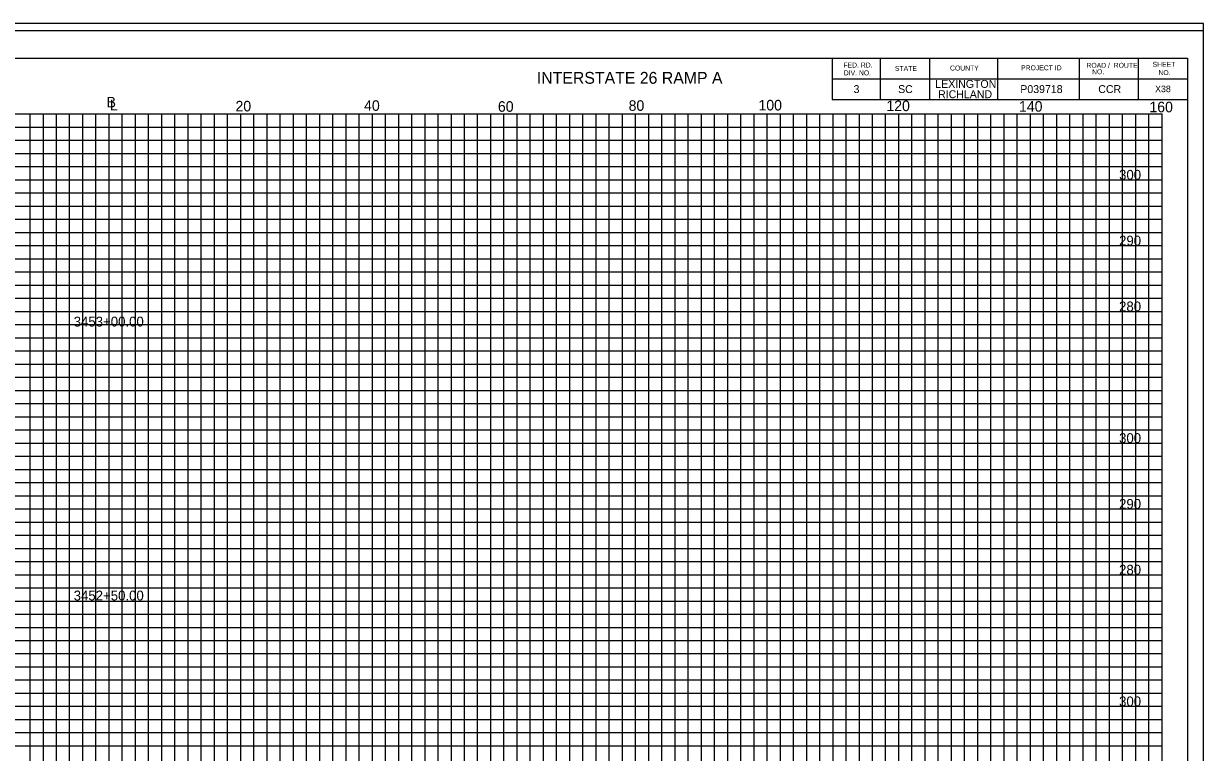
# Model space of a CAD drawing. Extents: x 967 to 1326, y 964 to 3704.
# Drawn here: x 1147 to 1326.3, y 2473 to 2583.7 of the extents above; entities that cross this region are included whole.
import ezdxf

# ---------------------------------------------------------------- set-up
doc = ezdxf.new("R2010")
doc.units = 0
for name, color, linetype in [('Default', 7, 'Continuous'), ('RD_SHT_Bndy', 7, 'Continuous'), ('RD_SHT_IplotShp', 7, 'Continuous'), ('RD_SHT_MjGrid', 7, 'Continuous'), ('RD_SHT_MnGrid', 7, 'Continuous'), ('RD_SHT_TX', 7, 'Continuous'), ('RD_XS_TX_Station', 7, 'Continuous')]:
    doc.layers.add(name, color=color, linetype=linetype)

msp = doc.modelspace()

# ---------------------------------------------------------------- linework, layer by layer
at = {"layer": 'RD_SHT_Bndy'}
for p, q in [((996.11, 2578.46), (1323.89, 2578.46)), ((1269.89, 2578.46), (1269.89, 2572.21)), ((1277.14, 2578.46), (1277.14, 2572.21)), ((1284.64, 2578.46), (1284.64, 2572.21)), ((1295, 2578.46), (1295, 2572.21)), ((1307.43, 2578.46), (1307.43, 2572.21)), ((1316.39, 2578.46), (1316.39, 2572.21)), ((1323.89, 2578.46), (1323.89, 2368.98)), ((1269.89, 2575.33), (1323.89, 2575.33)), ((1269.89, 2572.21), (1323.89, 2572.21))]:
    msp.add_line(p, q, dxfattribs=at)
at = {"layer": 'RD_SHT_IplotShp'}
for points in [[(967.41, 2363.72), (1326.28, 2363.72), (1326.28, 2583.72), (967.41, 2583.72)], [(988.52, 2364.84), (1326.28, 2364.84), (1326.28, 2582.6), (988.52, 2582.6)]]:
    msp.add_lwpolyline(points, close=True, dxfattribs=at)
at = {"layer": 'RD_SHT_MjGrid'}
for p, q in [((1000, 2570), (1320, 2570)), ((1150, 2400), (1150, 2570)), ((1160, 2400), (1160, 2570)), ((1170, 2400), (1170, 2570)), ((1180, 2400), (1180, 2570)), ((1190, 2400), (1190, 2570)), ((1200, 2400), (1200, 2570)), ((1210, 2400), (1210, 2570)), ((1220, 2400), (1220, 2570)), ((1230, 2400), (1230, 2570)), ((1240, 2400), (1240, 2570)), ((1250, 2400), (1250, 2570)), ((1260, 2400), (1260, 2570)), ((1270, 2400), (1270, 2570)), ((1280, 2400), (1280, 2570)), ((1290, 2400), (1290, 2570)), ((1300, 2400), (1300, 2570)), ((1310, 2400), (1310, 2570)), ((1320, 2400), (1320, 2570)), ((1000, 2560), (1320, 2560)), ((1000, 2550), (1320, 2550)), ((1000, 2540), (1320, 2540)), ((1000, 2530), (1320, 2530)), ((1000, 2520), (1320, 2520)), ((1000, 2510), (1320, 2510)), ((1000, 2500), (1320, 2500)), ((1000, 2490), (1320, 2490)), ((1000, 2480), (1320, 2480))]:
    msp.add_line(p, q, dxfattribs=at)
at = {"layer": 'RD_SHT_MnGrid'}
for p, q in [((1148, 2400), (1148, 2570)), ((1152, 2400), (1152, 2570)), ((1154, 2400), (1154, 2570)), ((1156, 2400), (1156, 2570)), ((1158, 2400), (1158, 2570)), ((1162, 2400), (1162, 2570)), ((1164, 2400), (1164, 2570)), ((1166, 2400), (1166, 2570)), ((1168, 2400), (1168, 2570)), ((1172, 2400), (1172, 2570)), ((1174, 2400), (1174, 2570)), ((1176, 2400), (1176, 2570)), ((1178, 2400), (1178, 2570)), ((1182, 2400), (1182, 2570)), ((1184, 2400), (1184, 2570)), ((1186, 2400), (1186, 2570)), ((1188, 2400), (1188, 2570)), ((1192, 2400), (1192, 2570)), ((1194, 2400), (1194, 2570)), ((1196, 2400), (1196, 2570)), ((1198, 2400), (1198, 2570)), ((1202, 2400), (1202, 2570)), ((1204, 2400), (1204, 2570)), ((1206, 2400), (1206, 2570)), ((1208, 2400), (1208, 2570)), ((1212, 2400), (1212, 2570)), ((1214, 2400), (1214, 2570)), ((1216, 2400), (1216, 2570)), ((1218, 2400), (1218, 2570)), ((1222, 2400), (1222, 2570)), ((1224, 2400), (1224, 2570)), ((1226, 2400), (1226, 2570)), ((1228, 2400), (1228, 2570)), ((1232, 2400), (1232, 2570)), ((1234, 2400), (1234, 2570)), ((1236, 2400), (1236, 2570)), ((1238, 2400), (1238, 2570)), ((1242, 2400), (1242, 2570)), ((1244, 2400), (1244, 2570)), ((1246, 2400), (1246, 2570)), ((1248, 2400), (1248, 2570)), ((1252, 2400), (1252, 2570)), ((1254, 2400), (1254, 2570)), ((1256, 2400), (1256, 2570)), ((1258, 2400), (1258, 2570)), ((1262, 2400), (1262, 2570)), ((1264, 2400), (1264, 2570)), ((1266, 2400), (1266, 2570)), ((1268, 2400), (1268, 2570)), ((1272, 2400), (1272, 2570)), ((1274, 2400), (1274, 2570)), ((1276, 2400), (1276, 2570)), ((1278, 2400), (1278, 2570)), ((1282, 2400), (1282, 2570)), ((1284, 2400), (1284, 2570)), ((1286, 2400), (1286, 2570)), ((1288, 2400), (1288, 2570)), ((1292, 2400), (1292, 2570)), ((1294, 2400), (1294, 2570)), ((1296, 2400), (1296, 2570)), ((1298, 2400), (1298, 2570)), ((1302, 2400), (1302, 2570)), ((1304, 2400), (1304, 2570)), ((1306, 2400), (1306, 2570)), ((1308, 2400), (1308, 2570)), ((1312, 2400), (1312, 2570)), ((1314, 2400), (1314, 2570)), ((1316, 2400), (1316, 2570)), ((1318, 2400), (1318, 2570)), ((1000, 2568), (1320, 2568)), ((1000, 2566), (1320, 2566)), ((1000, 2564), (1320, 2564)), ((1000, 2562), (1320, 2562)), ((1000, 2558), (1320, 2558)), ((1000, 2556), (1320, 2556)), ((1000, 2554), (1320, 2554)), ((1000, 2552), (1320, 2552)), ((1000, 2548), (1320, 2548)), ((1000, 2546), (1320, 2546)), ((1000, 2544), (1320, 2544)), ((1000, 2542), (1320, 2542)), ((1000, 2538), (1320, 2538)), ((1000, 2536), (1320, 2536)), ((1000, 2534), (1320, 2534)), ((1000, 2532), (1320, 2532)), ((1000, 2528), (1320, 2528)), ((1000, 2526), (1320, 2526)), ((1000, 2524), (1320, 2524)), ((1000, 2522), (1320, 2522)), ((1000, 2518), (1320, 2518)), ((1000, 2516), (1320, 2516)), ((1000, 2514), (1320, 2514)), ((1000, 2512), (1320, 2512)), ((1000, 2508), (1320, 2508)), ((1000, 2506), (1320, 2506)), ((1000, 2504), (1320, 2504)), ((1000, 2502), (1320, 2502)), ((1000, 2498), (1320, 2498)), ((1000, 2496), (1320, 2496)), ((1000, 2494), (1320, 2494)), ((1000, 2492), (1320, 2492)), ((1000, 2488), (1320, 2488)), ((1000, 2486), (1320, 2486)), ((1000, 2484), (1320, 2484)), ((1000, 2482), (1320, 2482)), ((1000, 2478), (1320, 2478)), ((1000, 2476), (1320, 2476)), ((1000, 2474), (1320, 2474))]:
    msp.add_line(p, q, dxfattribs=at)
at = {"layer": 'RD_XS_TX_Station'}
msp.add_lwpolyline([(967.41, 2363.72), (1326.28, 2363.72), (1326.28, 2583.72), (967.41, 2583.72)], close=True, dxfattribs=at)

# ---------------------------------------------------------------- texts
at = {"layer": 'Default'}
for s, height, p in [('X38', 1, (1318.95, 2573.3)), ('300', 1.5, (1313.47, 2560)), ('290', 1.5, (1313.47, 2550)), ('280', 1.5, (1313.47, 2540)), ('3453+00.00', 1.5, (1154.61, 2537.7)), ('300', 1.5, (1313.47, 2520)), ('290', 1.5, (1313.47, 2510)), ('280', 1.5, (1313.47, 2500)), ('3452+50.00', 1.5, (1154.61, 2496.08)), ('300', 1.5, (1313.47, 2480))]:
    msp.add_text(s, height=height, dxfattribs=at).set_placement(p)
at = {"layer": 'RD_SHT_TX'}
msp.add_text('INTERSTATE 26 RAMP A', height=1.8, rotation=0, dxfattribs=at).set_placement((1224.99, 2574.58))
for s, height, p in [('FED. RD.', 0.75, (1271.58, 2577.05)), ('DIV. NO.', 0.75, (1271.64, 2575.86)), ('STATE', 0.75, (1279.41, 2576.53)), ('COUNTY', 0.75, (1287.78, 2576.59)), ('PROJECT ID', 0.75, (1298.58, 2576.63)), ('ROAD /  ROUTE', 0.75, (1308.51, 2577.01)), ('   NO.', 0.75, (1308.51, 2576.03)), ('SHEET', 0.75, (1318.56, 2577.16)), ('NO.', 0.75, (1319.45, 2575.91)), ('LEXINGTON', 1.2, (1285.54, 2573.96)), ('3', 1.2, (1273.12, 2573.17)), ('SC', 1.2, (1279.89, 2573.17)), ('RICHLAND', 1.2, (1285.97, 2572.39)), ('P039718', 1.2, (1298.46, 2573.17)), ('CCR', 1.2, (1310.31, 2573.17)), ('B', 1.6, (1159.61, 2570.99)), ('L', 1.6, (1160.12, 2570.54)), ('20', 1.6, (1179.2, 2570.38)), ('40', 1.6, (1198.74, 2570.47)), ('60', 1.6, (1219.08, 2570.33)), ('80', 1.6, (1238.94, 2570.47)), ('100', 1.6, (1258.67, 2570.53)), ('120', 1.6, (1278.11, 2570.43)), ('140', 1.6, (1298.26, 2570.34)), ('160', 1.6, (1318.08, 2570.25))]:
    msp.add_text(s, height=height, dxfattribs=at).set_placement(p)

doc.saveas('drawing.dxf')
